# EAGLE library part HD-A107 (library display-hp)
LED DISPLAY + - 1/2 character, decimal point right
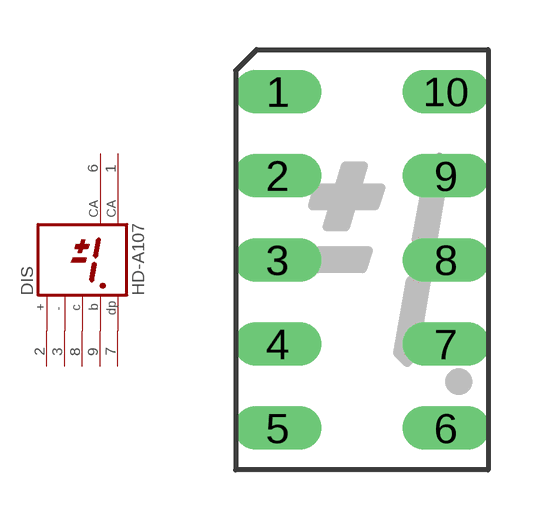
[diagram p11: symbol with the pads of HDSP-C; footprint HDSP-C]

Designator prefix DIS

## HD-A107 (OC_FARNELL: unknown; OC_NEWARK: unknown)  [HDSP-C]
1  CA  pas
2  +  pas
3  -  pas
6  CA  pas
7  DP  pas
8  C  pas
9  B  pas

## Footprint HDSP-C (pad centres in mm)
LED DISPLAY 8-mm + - 1/2 character, decimal point right
drill 0.813 long: 1 -2.54,5.08; 2 -2.54,2.54; 3 -2.54,0; 4 -2.54,-2.54; 5 -2.54,-5.08; 6 2.54,-5.08; 7 2.54,-2.54; 8 2.54,0; 9 2.54,2.54; 10 2.54,5.08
